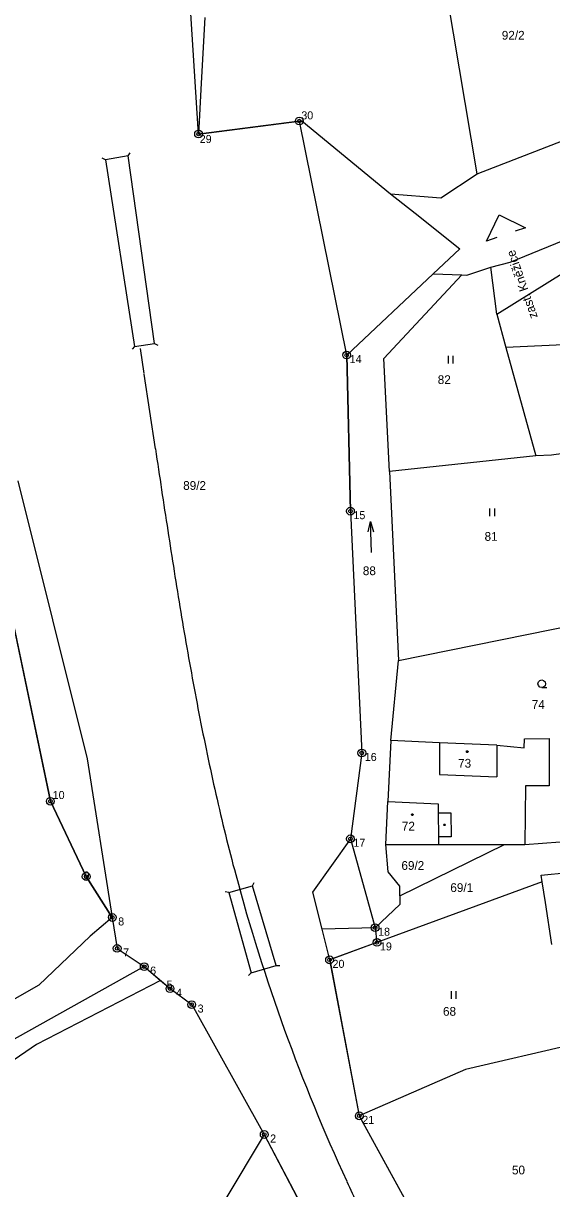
# Model space of a CAD drawing. Extents: x -812394 to -807601, y -1013097 to -1009266.
# Drawn here: x -809883 to -809780.5, y -1011039 to -1010813 of the extents above; entities that cross this region are included whole.
import ezdxf

# ---------------------------------------------------------------- set-up
doc = ezdxf.new("R2010")
doc.units = 0
for name, color, linetype in [('body', 7, 'Continuous'), ('cisla', 7, 'Continuous'), ('Default', 7, 'Continuous'), ('KN_HRANICE', 7, 'Continuous'), ('KN_KULTURY', 7, 'Continuous'), ('KN_PARCELY', 7, 'Continuous'), ('KN_SLUCKY', 7, 'Continuous'), ('obvod_stavby', 7, 'Continuous'), ('SO02 - Železniční svršek', 7, 'Continuous')]:
    doc.layers.add(name, color=color, linetype=linetype)

# ---------------------------------------------------------------- blocks, each defined once
blk = doc.blocks.new('4201')
at = {"layer": 'Default'}
blk.add_line((0, 0), (-0.5, -0.5), dxfattribs=at)
blk = doc.blocks.new('304')
at = {"layer": 'Default'}
blk.add_lwpolyline([(0, 0), (-0.38, 0.1), (-0.65, 0.37), (-0.75, 0.74), (-0.65, 1.11), (-0.38, 1.38), (-0.01, 1.48), (0.36, 1.38), (0.63, 1.11), (0.73, 0.73), (0.63, 0.35), (0.36, 0.08), (-0.02, -0.02), (0.98, -0.02)], dxfattribs=at)
blk = doc.blocks.new('306')
at = {"layer": 'Default'}
for p, q in [((-0.5, 1.5), (-0.5, 0)), ((0.5, 0), (0.5, 1.5))]:
    blk.add_line(p, q, dxfattribs=at)
blk = doc.blocks.new('802')
at = {"layer": 'Default'}
blk.add_line((-3, 0), (3, 0), dxfattribs=at)
blk.add_lwpolyline([(1, 0.5), (3, 0), (1, -0.5)], dxfattribs=at)
blk = doc.blocks.new('402')
at = {"layer": 'Default'}
blk.add_lwpolyline([(0.09, 0.15), (0.18, 0), (0.09, -0.15), (-0.09, -0.15), (-0.18, 0), (-0.09, 0.15), (0.09, 0.15)], dxfattribs=at)

msp = doc.modelspace()

# ---------------------------------------------------------------- linework, layer by layer
at = {"layer": 'body'}
for p, q in [((-809829.44, -1010832), (-809829.44, -1010832)), ((-809848.99, -1010834.52), (-809848.99, -1010834.52)), ((-809820.27, -1010877.38), (-809820.27, -1010877.38)), ((-809819.54, -1010907.65), (-809819.54, -1010907.65)), ((-809817.34, -1010954.54), (-809817.34, -1010954.54)), ((-809870.58, -1010955.65), (-809870.58, -1010955.65)), ((-809819.55, -1010971.19), (-809819.55, -1010971.19)), ((-809865.72, -1010986.44), (-809865.72, -1010986.44)), ((-809814.76, -1010988.43), (-809814.76, -1010988.43)), ((-809864.77, -1010992.44), (-809864.77, -1010992.44)), ((-809814.4, -1010991.28), (-809814.4, -1010991.28)), ((-809823.59, -1010994.66), (-809823.59, -1010994.66)), ((-809859.52, -1010995.97), (-809859.52, -1010995.97)), ((-809856.34, -1010998.68), (-809856.34, -1010998.68)), ((-809854.51, -1011000.24), (-809854.51, -1011000.24)), ((-809850.32, -1011003.33), (-809850.32, -1011003.33)), ((-809817.83, -1011024.91), (-809817.83, -1011024.91)), ((-809836.26, -1011028.53), (-809836.26, -1011028.53))]:
    msp.add_line(p, q, dxfattribs=at)
for centre, radius in [((-809829.44, -1010832), 0.75), ((-809829.44, -1010832), 0.35), ((-809848.99, -1010834.52), 0.75), ((-809848.99, -1010834.52), 0.35), ((-809820.27, -1010877.38), 0.75), ((-809820.27, -1010877.38), 0.35), ((-809819.54, -1010907.65), 0.75), ((-809819.54, -1010907.65), 0.35), ((-809817.34, -1010954.54), 0.75), ((-809817.34, -1010954.54), 0.35), ((-809877.71, -1010963.9), 0.75), ((-809877.71, -1010963.9), 0.35), ((-809819.55, -1010971.19), 0.75), ((-809819.55, -1010971.19), 0.35), ((-809870.77, -1010978.5), 0.75), ((-809870.77, -1010978.5), 0.35), ((-809865.72, -1010986.44), 0.75), ((-809865.72, -1010986.44), 0.35), ((-809814.76, -1010988.43), 0.75), ((-809814.76, -1010988.43), 0.35), ((-809814.4, -1010991.28), 0.75), ((-809814.4, -1010991.28), 0.35), ((-809864.77, -1010992.44), 0.75), ((-809864.77, -1010992.44), 0.35), ((-809859.52, -1010995.97), 0.75), ((-809859.52, -1010995.97), 0.35), ((-809823.59, -1010994.66), 0.75), ((-809823.59, -1010994.66), 0.35), ((-809854.51, -1011000.24), 0.75), ((-809854.51, -1011000.24), 0.35), ((-809850.32, -1011003.33), 0.75), ((-809850.32, -1011003.33), 0.35), ((-809817.83, -1011024.91), 0.75), ((-809817.83, -1011024.91), 0.35), ((-809836.26, -1011028.53), 0.75), ((-809836.26, -1011028.53), 0.35)]:
    msp.add_circle(centre, radius, dxfattribs=at)
at = {"layer": 'Default'}
msp.add_lwpolyline([(-809791.17, -1010854.59), (-809793.18, -1010855.28), (-809790.68, -1010850.2), (-809785.61, -1010852.7), (-809787.62, -1010853.38)], dxfattribs=at)
at = {"layer": 'KN_HRANICE'}
for p, q in [((-809795, -1010842.25), (-809802.82, -1010795.47)), ((-809847.8, -1010811.91), (-809848.47, -1010824.63)), ((-809848.47, -1010824.63), (-809848.99, -1010834.52)), ((-809848.99, -1010834.52), (-809828.94, -1010831.94)), ((-809828.94, -1010831.94), (-809811.76, -1010846.11)), ((-809795, -1010842.25), (-809768.91, -1010832.11)), ((-809788.59, -1010859.35), (-809744.44, -1010841.28)), ((-809802.04, -1010846.92), (-809795, -1010842.25)), ((-809811.76, -1010846.11), (-809802.04, -1010846.92)), ((-809811.76, -1010846.11), (-809806.99, -1010849.89)), ((-809806.99, -1010849.89), (-809798.33, -1010856.76)), ((-809803.49, -1010861.61), (-809798.33, -1010856.76)), ((-809792.34, -1010860.31), (-809788.59, -1010859.35)), ((-809820.27, -1010877.38), (-809803.49, -1010861.61)), ((-809813.07, -1010878.06), (-809797.95, -1010861.84)), ((-809803.49, -1010861.61), (-809797.95, -1010861.84)), ((-809797.95, -1010861.84), (-809796.98, -1010861.88)), ((-809796.98, -1010861.88), (-809792.34, -1010860.31)), ((-809791.19, -1010869.46), (-809792.34, -1010860.31)), ((-809791.19, -1010869.46), (-809777.96, -1010861.22)), ((-809791.19, -1010869.46), (-809789.4, -1010875.94)), ((-809760.65, -1010874.53), (-809789.4, -1010875.94)), ((-809820.27, -1010877.38), (-809819.54, -1010907.65)), ((-809811.97, -1010899.94), (-809813.07, -1010878.06)), ((-809789.4, -1010875.94), (-809783.61, -1010896.9)), ((-809772.62, -1010895.72), (-809780.58, -1010896.79)), ((-809891.53, -1010897.94), (-809877.71, -1010963.9)), ((-809783.61, -1010896.9), (-809811.97, -1010899.94)), ((-809780.58, -1010896.79), (-809783.61, -1010896.9)), ((-809811.97, -1010899.94), (-809810.23, -1010936.6)), ((-809883.99, -1010901.78), (-809870.58, -1010955.65)), ((-809819.54, -1010907.65), (-809817.34, -1010954.54)), ((-809810.23, -1010936.6), (-809774.68, -1010929.4)), ((-809811.73, -1010952.15), (-809810.23, -1010936.6)), ((-809811.73, -1010952.15), (-809812.29, -1010963.93)), ((-809802.28, -1010952.55), (-809811.73, -1010952.15)), ((-809791.19, -1010953.02), (-809802.28, -1010952.55)), ((-809802.28, -1010952.55), (-809802.28, -1010958.7)), ((-809785.87, -1010953.57), (-809785.81, -1010951.78)), ((-809785.81, -1010951.78), (-809780.99, -1010951.72)), ((-809780.99, -1010951.72), (-809780.99, -1010960.93)), ((-809817.34, -1010954.54), (-809819.55, -1010971.19)), ((-809791.19, -1010953.02), (-809785.87, -1010953.57)), ((-809791.19, -1010953.02), (-809791.19, -1010959.17)), ((-809870.58, -1010955.65), (-809865.72, -1010986.44)), ((-809802.28, -1010958.7), (-809791.19, -1010959.17)), ((-809785.63, -1010960.93), (-809785.75, -1010972.3)), ((-809780.99, -1010960.93), (-809785.63, -1010960.93)), ((-809877.71, -1010963.9), (-809870.77, -1010978.5)), ((-809812.69, -1010972.27), (-809812.29, -1010963.93)), ((-809785.75, -1010972.3), (-809762.22, -1010970.5)), ((-809819.55, -1010971.19), (-809826.87, -1010981.55)), ((-809812.22, -1010977.58), (-809812.69, -1010972.27)), ((-809812.69, -1010972.27), (-809802.49, -1010972.27)), ((-809809.94, -1010982.24), (-809789.65, -1010972.3)), ((-809802.49, -1010972.27), (-809789.65, -1010972.3)), ((-809789.65, -1010972.3), (-809785.75, -1010972.3)), ((-809870.77, -1010978.5), (-809865.72, -1010986.44)), ((-809782.36, -1010979.51), (-809823.59, -1010994.66)), ((-809809.94, -1010980.34), (-809812.22, -1010977.58)), ((-809782.57, -1010978.23), (-809777.31, -1010977.72)), ((-809782.36, -1010979.51), (-809782.57, -1010978.23)), ((-809781.71, -1010983.51), (-809782.36, -1010979.51)), ((-809826.87, -1010981.55), (-809825.08, -1010988.69)), ((-809809.94, -1010982.24), (-809809.94, -1010980.34)), ((-809809.94, -1010983.94), (-809814.76, -1010988.43)), ((-809809.94, -1010982.24), (-809809.94, -1010983.94)), ((-809780.48, -1010991.7), (-809781.71, -1010983.51)), ((-809865.72, -1010986.44), (-809864.77, -1010992.44)), ((-809814.76, -1010988.43), (-809825.08, -1010988.69)), ((-809825.08, -1010988.69), (-809823.59, -1010994.66)), ((-809864.77, -1010992.44), (-809859.52, -1010995.97)), ((-809823.59, -1010994.66), (-809817.83, -1011024.91)), ((-809859.52, -1010995.97), (-809908, -1011022.99)), ((-809859.52, -1010995.97), (-809856.34, -1010998.68)), ((-809856.34, -1010998.68), (-809854.51, -1011000.24)), ((-809854.51, -1011000.24), (-809850.32, -1011003.33)), ((-809850.32, -1011003.33), (-809836.26, -1011028.53)), ((-809776.12, -1011010.98), (-809797.21, -1011015.92)), ((-809797.21, -1011015.92), (-809817.83, -1011024.91)), ((-809817.83, -1011024.91), (-809805.06, -1011048.21)), ((-809836.26, -1011028.53), (-809810.89, -1011076.81))]:
    msp.add_line(p, q, dxfattribs=at)
for points in [[(-809865.72, -1010986.44), (-809869.99, -1010990.08), (-809879.97, -1010999.54), (-809901.79, -1011011.97), (-809939.8, -1011020.34), (-809964.35, -1011020.31), (-809988.57, -1011017.29)], [(-809856.34, -1010998.68), (-809880.39, -1011011.09), (-809908.29, -1011030.22), (-809924.26, -1011031.19), (-809964.98, -1011028.8), (-809990.74, -1011026.75)], [(-809836.26, -1011028.53), (-809843.91, -1011041.24), (-809850.36, -1011047.46), (-809913.17, -1011066.15), (-809940.27, -1011066.63), (-809925.64, -1011129.13), (-809925.02, -1011131.63)]]:
    msp.add_lwpolyline(points, dxfattribs=at)
at = {"layer": 'KN_SLUCKY'}
for p, q in [((-809862.62, -1010838.73), (-809867.02, -1010839.54)), ((-809867.02, -1010839.54), (-809861.38, -1010875.75)), ((-809857.55, -1010875.16), (-809862.62, -1010838.73)), ((-809861.38, -1010875.75), (-809857.55, -1010875.16)), ((-809812.29, -1010963.93), (-809802.55, -1010964.39)), ((-809802.55, -1010964.39), (-809802.54, -1010966.18)), ((-809802.54, -1010966.18), (-809800.07, -1010966.17)), ((-809802.54, -1010966.18), (-809802.5, -1010970.8)), ((-809800.07, -1010966.17), (-809800.04, -1010970.79)), ((-809800.04, -1010970.79), (-809802.5, -1010970.8)), ((-809802.5, -1010970.8), (-809802.49, -1010972.27)), ((-809843.14, -1010981.57), (-809838.55, -1010980.29)), ((-809843.14, -1010981.57), (-809838.78, -1010997.2)), ((-809833.94, -1010995.74), (-809838.55, -1010980.29)), ((-809838.78, -1010997.2), (-809833.94, -1010995.74))]:
    msp.add_line(p, q, dxfattribs=at)
at = {"layer": 'obvod_stavby'}
for points in [[(-809819.54, -1010907.68), (-809820.27, -1010877.38), (-809829.44, -1010832), (-809848.99, -1010834.52), (-809851.28, -1010798.84), (-809898.47, -1010814.6), (-809898.21, -1010828.41), (-809894.78, -1010861.65), (-809893.92, -1010865.41), (-809892.39, -1010868.68), (-809890.33, -1010872.36)], [(-809865.72, -1010986.44), (-809870.77, -1010978.5), (-809877.71, -1010963.9), (-809891.53, -1010897.94), (-809892.98, -1010891.43), (-809900.04, -1010876.16), (-809894.12, -1010873.72), (-809890.33, -1010872.36)], [(-809819.54, -1010907.65), (-809819.54, -1010907.65), (-809817.34, -1010954.54), (-809819.55, -1010971.16), (-809814.76, -1010988.43), (-809814.4, -1010991.28), (-809823.56, -1010994.65), (-809817.83, -1011024.91), (-809805.06, -1011048.21), (-809802.44, -1011052.2)], [(-809865.72, -1010986.44), (-809864.77, -1010992.44), (-809859.52, -1010995.97), (-809854.51, -1011000.24), (-809850.32, -1011003.33), (-809836.26, -1011028.53), (-809823.58, -1011052.67), (-809818.58, -1011062.18)]]:
    msp.add_lwpolyline(points, dxfattribs=at)
at = {"layer": 'SO02 - Železniční svršek'}
for p, q in [((-809859.53, -1010880.95), (-809860.25, -1010876.12)), ((-809857.34, -1010895.59), (-809859.51, -1010881.07))]:
    msp.add_line(p, q, dxfattribs=at)
msp.add_lwpolyline([(-809857.34, -1010895.59), (-809857.19, -1010896.58), (-809857.05, -1010897.56), (-809856.9, -1010898.55), (-809856.75, -1010899.54), (-809856.6, -1010900.53), (-809856.45, -1010901.52), (-809856.3, -1010902.51), (-809856.15, -1010903.5), (-809856.01, -1010904.49), (-809855.86, -1010905.48), (-809855.71, -1010906.46), (-809855.56, -1010907.45), (-809855.41, -1010908.44), (-809855.26, -1010909.43), (-809855.1, -1010910.42), (-809854.95, -1010911.41), (-809854.8, -1010912.4), (-809854.65, -1010913.38), (-809854.49, -1010914.37), (-809854.34, -1010915.36), (-809854.19, -1010916.35), (-809854.03, -1010917.34), (-809853.87, -1010918.32), (-809853.72, -1010919.31), (-809853.56, -1010920.3), (-809853.4, -1010921.29), (-809853.24, -1010922.27), (-809853.08, -1010923.26), (-809852.92, -1010924.25), (-809852.76, -1010925.23), (-809852.6, -1010926.22), (-809852.43, -1010927.21), (-809852.27, -1010928.19), (-809852.1, -1010929.18), (-809851.94, -1010930.17), (-809851.77, -1010931.15), (-809851.6, -1010932.14), (-809851.43, -1010933.12), (-809851.26, -1010934.11), (-809851.09, -1010935.09), (-809850.91, -1010936.08), (-809850.74, -1010937.06), (-809850.56, -1010938.05), (-809850.38, -1010939.03), (-809850.2, -1010940.02), (-809850.02, -1010941), (-809849.84, -1010941.98), (-809849.66, -1010942.96), (-809849.47, -1010943.95), (-809849.28, -1010944.93), (-809849.1, -1010945.91), (-809848.91, -1010946.89), (-809848.71, -1010947.88), (-809848.52, -1010948.86), (-809848.33, -1010949.84), (-809848.13, -1010950.82), (-809847.93, -1010951.8), (-809847.73, -1010952.78), (-809847.53, -1010953.76), (-809847.32, -1010954.74), (-809847.12, -1010955.71), (-809846.91, -1010956.69), (-809846.7, -1010957.67), (-809846.49, -1010958.65), (-809846.28, -1010959.62), (-809846.06, -1010960.6), (-809845.84, -1010961.58), (-809845.62, -1010962.55), (-809845.4, -1010963.53), (-809845.18, -1010964.5), (-809844.95, -1010965.48), (-809844.72, -1010966.45), (-809844.49, -1010967.42), (-809844.26, -1010968.4), (-809844.02, -1010969.37), (-809843.78, -1010970.34), (-809843.54, -1010971.31), (-809843.3, -1010972.28), (-809843.06, -1010973.25), (-809842.81, -1010974.22), (-809842.56, -1010975.19), (-809842.31, -1010976.15), (-809842.05, -1010977.12), (-809841.79, -1010978.09)], dxfattribs=at)
for start, end in [(195.0021, 204.7941), (204.8126, 206.3264)]:
    msp.add_arc((-809483.92, -1010882.18), 370.5, start, end, dxfattribs=at)

# ---------------------------------------------------------------- block references
at = {"layer": 'KN_KULTURY'}
for name, p in [('306', (-809800.11, -1010879.02)), ('306', (-809792.06, -1010908.62)), ('304', (-809782.45, -1010941.85)), ('402', (-809796.9, -1010954.29)), ('402', (-809807.54, -1010966.52)), ('402', (-809801.31, -1010968.47)), ('306', (-809799.54, -1011002.22))]:
    msp.add_blockref(name, p, dxfattribs=at)
at = {"layer": 'KN_KULTURY', "rotation": 91.845135}
msp.add_blockref('802', (-809815.56, -1010912.67), dxfattribs=at)
at = {"layer": 'KN_SLUCKY'}
for p, rotation in [((-809867.02, -1010839.54), -71.80222900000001), ((-809862.62, -1010838.73), -169.72071599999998), ((-809857.55, -1010875.16), 110.92462900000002), ((-809838.55, -1010980.29), -161.41282800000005), ((-809843.14, -1010981.57), -54.89997400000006), ((-809833.94, -1010995.74), 131.608406)]:
    msp.add_blockref('4201', p, dxfattribs=dict(at, rotation=rotation))
for p in [(-809861.38, -1010875.75), (-809838.78, -1010997.2)]:
    msp.add_blockref('4201', p, dxfattribs=at)

# ---------------------------------------------------------------- texts
at = {"layer": 'cisla'}
for s, p in [(' 30', (-809829.64, -1010831.67)), (' 29', (-809849.34, -1010836.26)), (' 14', (-809820.27, -1010878.93)), (' 15', (-809819.54, -1010909.2)), (' 16', (-809817.34, -1010956.09)), (' 10', (-809877.84, -1010963.47)), (' 17', (-809819.55, -1010972.74)), ('  9', (-809872.42, -1010979.06)), ('  8', (-809865.72, -1010987.99)), (' 18', (-809814.76, -1010989.98)), ('  7', (-809864.77, -1010993.99)), (' 19', (-809814.4, -1010992.83)), (' 20', (-809823.59, -1010996.21)), ('  6', (-809859.52, -1010997.52)), ('  5', (-809856.34, -1011000.23)), ('  4', (-809854.51, -1011001.79)), ('  3', (-809850.32, -1011004.88)), (' 21', (-809817.83, -1011026.46)), ('  2', (-809836.26, -1011030.08))]:
    msp.add_text(s, height=1.552, dxfattribs=at).set_placement(p)
at = {"layer": 'Default'}
msp.add_text('zast. Kněžice', height=1.75, rotation=108.9609, dxfattribs=at).set_placement((-809783.21, -1010869.98))
at = {"layer": 'KN_PARCELY'}
for s, p in [('92/2', (-809790.2, -1010816.22)), ('82', (-809802.62, -1010883)), ('89/2', (-809851.97, -1010903.52)), ('81', (-809793.54, -1010913.4)), ('88', (-809817.14, -1010920.06)), ('74', (-809784.39, -1010946)), ('73', (-809798.67, -1010957.39)), ('72', (-809809.57, -1010969.58)), ('69/2', (-809809.66, -1010977.21)), ('69/1', (-809800.18, -1010981.5)), ('68', (-809801.6, -1011005.5)), ('50', (-809788.23, -1011036.26))]:
    msp.add_text(s, height=1.7, dxfattribs=at).set_placement(p)

doc.saveas('drawing.dxf')
